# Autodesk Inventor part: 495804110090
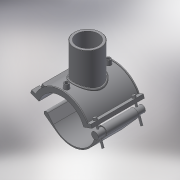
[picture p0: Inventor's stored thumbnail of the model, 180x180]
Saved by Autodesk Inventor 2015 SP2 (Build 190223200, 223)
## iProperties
Created: 2017-07
Part Number: 495804110090
Material: Generic
Description: PLASSON BRANCH SADDLE 110-90
Document SubType Name: Modeling
Designer: KIM
Density: 1 g/cm^3
Appearance: Default
Author: KIM
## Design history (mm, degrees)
derived "495804.ipt"
feature "Solid1::495804.ipt"
feature "Solid2::495804.ipt"
tag "TaggingFeature1"
body "Solid1"
body "Solid2"
other parameters: "d2" = 162, "d3" = 27.5, "d4" = 176, "d5" = 0, "d6" = 0.1, "d8" = 0, "d19" = 6, "d20" = 6, "d21" = 105.6, "d23" = 0, "d24" = 52.8, "d26" = 0, "d27" = 3, "d28" = 3, "d29" = 3, "d30" = 36.66667, "d31" = 6, "d32" = 0, "d33" = 0, "d34" = 0.6, "d40" = 72.8, "d41" = 99, "d43" = 0, "d45" = 0, "d47" = 175, "d50" = 0, "d70" = 15, "d72" = 0, "d73" = 6, "d75" = 5, "d76" = 0, "d77" = 5.5, "d78" = 85, "d79" = 15, "d80" = 70.4, "d82" = 5 deg, "d84" = 4, "d85" = 14, "d86" = 0, "d87" = 3, "d88" = 0, "d89" = 1, "d90" = 1, "d91" = 140.8, "d92" = 0, "d93" = 0.5, "d94" = 57.89474, "d96" = 142.8, "d97" = 3.52, "d98" = 0, "d102" = 2.7, "d103" = 72, "d105" = 0, "d109" = -35, "d117" = 0.9, "d120" = 140 deg, "d121" = 24.228, "d122" = 20 deg, "d124" = 84, "d126" = 0, "d143" = 115.5, "d150" = 19.8, "d159" = 6, "d161" = 2.75, "d162" = 105.6, "d163" = 0, "d167" = 22, "d168" = 63.63636, "d173" = 1, "d175" = 55, "d176" = 20 deg, "d177" = 7.7, "d178" = 27, "d180" = 0, "d185" = 57.2, "d186" = 57.2, "d188" = 9, "d189" = 7.7, "d190" = 0, "d191" = 105, "d200" = 15, "d202" = 0, "d216" = 158.4, "d217" = 0, "d221" = 65.12, "d222" = 7.7, "d223" = 4.62, "d224" = 55, "d225" = 4.62, "d227" = 15.84, "d230" = 75.9, "d236" = 20 deg, "d237" = 76, "d238" = 20 deg, "d239" = 7.7, "B_" = 162, "H_" = 105, "L_" = 176, "d_t" = 6, "d148" = 2.75, "d160" = 2.75
